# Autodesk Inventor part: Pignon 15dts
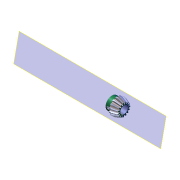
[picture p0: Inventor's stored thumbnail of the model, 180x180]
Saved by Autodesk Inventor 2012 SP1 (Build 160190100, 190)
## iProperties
Created: 2014-12
Part Number: Pignon 15dts
Material: Default
Document SubType Name: Modeling
Designer: Bruno
Density: 1 g/cm^3
Mass: 1.19463 g
Surface Area: 14.1625 cm^2
Volume: 1.19463 cm^3
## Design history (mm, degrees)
node "Pignon 15dts1"
node "Plan de construction1"
sketch "Esquisse3"
  geometry: L1 (16.279, -6.41)-(16.279, -4.886) reference; L2 (21.189, -8.381)-(16.279, -6.41) reference; L3 (24.399, -6.65)-(24.399, 6.65) reference; L4 (24.399, 0)-(15.145, 0); L5 (0.315, 0)-(0.315, -10.947); L6 (16.279, -5.648)-(23.841, -7.97); 2 further points
  constraints: 6 end point, 2 midpoint, 2 perpendicular, 4 other
  dimensions: "d6" = 17.0724 deg angle of L4 L6
feature "SrfRévolution2" sketch "Esquisse3" dims angle "d7" = 90 deg
node "Pignon 15dts"
node "Base1"
node "Boucle projetée1"
body "Srf3"
